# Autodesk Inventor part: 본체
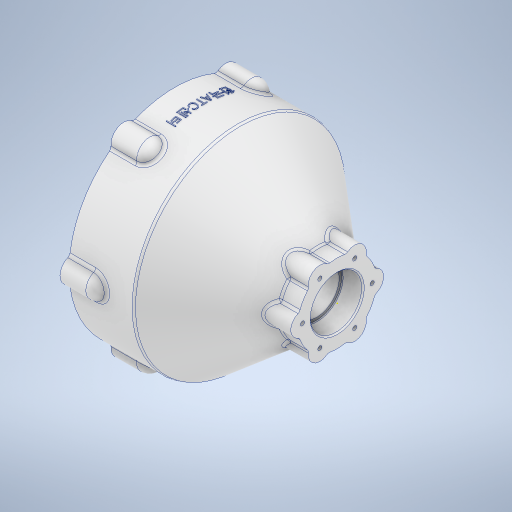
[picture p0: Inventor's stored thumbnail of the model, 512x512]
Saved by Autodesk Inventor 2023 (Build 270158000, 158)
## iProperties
Created: 2026-05
Part Number: 본체
Material: 알루미늄 6061
Document SubType Name: Modeling
Designer: home
Density: 2.7 g/cm^3
Appearance: 알루미늄 - 평지
Mass: 1989.24 g
Surface Area: 1183.24 cm^2
Volume: 736.757 cm^3
Author: home
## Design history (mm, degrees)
sketch "스케치1"
  geometry: L1 (-111.313, 0)-(0, 0); L2 (-126, 0)-(-126, 82); L3 (-126, 82)-(-76, 82); L4 (-76, 82)-(-14.625, 30.5); L5 (-14.625, 30.5)-(0, 30.5); L6 (0, 30.5)-(0, 0); L7 (-126, 73)-(-89, 73); L8 (-89, 73)-(-89, 68); L9 (-89, 68)-(-84, 68); L10 (-84, 68)-(-84, 56); L11 (-84, 56)-(-64, 56); L12 (-64, 56)-(-64, 40); L13 (-64, 40)-(-48, 40); L14 (-48, 40)-(-48, 37); L15 (-48, 37)-(-44, 37); L16 (-44, 37)-(-44, 20); L17 (-44, 20)-(-32, 20); L18 (-32, 20)-(-32, 17.5); L19 (-32, 17.5)-(-16, 17.5); L20 (-16, 17.5)-(-16, 20); L21 (-16, 20)-(0, 20); 2 further points
  constraints: 42 end point, 15 perpendicular, 5 point on line, 2 horizontal, 2 midpoint, 1 parallel, 1 vertical
  dimensions: "d0" = 126 distance from line of L1.end L2; "d1" = 164 diameter of point (-101, 82) L1; "d2" = 146 diameter of L7 L1; "d3" = 136 diameter of L9 L1; "d4" = 112 diameter of L11 L1; "d5" = 80 diameter of L13 L1; "d6" = 74 diameter of L15 L1; "d7" = 40 diameter of L17 L1; "d9" = 16 horizontal distance of L1.end point (-16, 18.75); "d10" = 37 distance of L7.start L7.end; "d11" = 94 distance from line of L2.start L18; "d12" = 12 distance of L16.end L17.end; "d16" = 50 distance of L2.end L3.end; "d17" = 126 horizontal distance of L1.end L2.end (derived); "d18" = 40 deg angle of L4 L3; "d19" = 61 diameter of L5 L1; "d20" = 40 diameter of L21 L1 (derived); "d21" = 5 distance of L8.end L9.end; "d22" = 25 distance between parallel lines of L12 L8; "d23" = 16 distance of L12.end L13.end; "d24" = 4 distance of L14.end L15.end (derived); "d25" = 35 diameter of L19 L1
revolve "회전1" sketch "스케치1" stored, may be unused: angle "d26" = 90 deg
sketch "스케치2"
  geometry: L1 (0, 0)-(79, 0); A1 r 79 centre (0, 0) between (78.367, -9.98) and (78.367, 9.98); A2 r 10 centre (79, 0) between (78.367, -9.98) and (78.367, 9.98); A3 r 79 centre (0, 0) between (78.367, -9.98) and (78.367, 9.98); 2 further points
  constraints: 8 point on circle, 4 coincident, 3 centre point, 2 end point, 1 horizontal
  dimensions: "d27" = 158 diameter of A1; "d28" = 20 diameter of A2
extrude "돌출1" join sketch "스케치2" distance "d29" = 20; taper "d30" = 0 deg
sketch "스케치4"
  geometry: L1 (-79, 0)-(0, 0)
  constraints: 2 end point, 1 horizontal
  dimensions: "d41" = 79 distance of L1.start L1.end
hole "구멍2" sketch "스케치4" at (0, 0) diameter "d42" = 4.917; stored, may be unused: countersink angle "d46" = 90 deg, drill point angle "d48" = 118 deg; dims "d43" = 12, "d44" = 4, "d45" = 2, "d47" = 14
sketch "스케치5"
  geometry: L1 (0, 0)-(62, 0)
  constraints: 2 end point, 1 horizontal
  dimensions: "d52" = 62 distance of L1.start L1.end
hole "구멍3" sketch "스케치5" at (62, 0) diameter "d53" = 3.242; stored, may be unused: countersink angle "d57" = 90 deg, drill point angle "d59" = 118 deg; dims "d54" = 8, "d55" = 4, "d56" = 2, "d58" = 10
sketch "스케치6"
  geometry: A1 r 27 centre (0, 0) between (-25.5, 8.874) and (-25.5, -8.874); A2 r 9 centre (-27, 0) between (-25.5, 8.874) and (-25.5, -8.874); A3 r 27 centre (0, 0) between (-25.5, 8.874) and (-25.5, -8.874); 1 further point
  constraints: 8 point on circle, 3 centre point, 2 coincident
  dimensions: "d63" = 54 diameter of A1; "d64" = 18 diameter of A2
extrude "돌출2" join sketch "스케치6" stored distance "d65" = 20; taper "d66" = 0 deg
sketch "스케치7"
  geometry: 1 further point
sketch "스케치8"
  geometry: L1 (27, 0)-(0, 0)
  constraints: 2 end point, 1 horizontal
  dimensions: "d70" = 27 distance of L1.start L1.end
hole "구멍4" sketch "스케치8" at (0, 0) diameter "d71" = 3.242; stored, may be unused: countersink angle "d75" = 90 deg, drill point angle "d77" = 118 deg; dims "d72" = 8, "d73" = 4, "d74" = 2, "d76" = 10
fillet "모깎기1" dims "d81" = 3
fillet "모깎기2" dims "d82" = 3
sketch "스케치9"
  geometry: L1 (106, 82)-(106, 81.424) reference; L2 (106, 89)-(106, 81.424) reference; L3 (106, 89)-(106, 89); L4 (106, 89)-(106, 79); L5 (96, 79)-(106, 79); A1 r 10 centre (106, 79) between (106, 89) and (96, 79); 4 further points
  constraints: 6 end point, 2 horizontal, 2 point on circle, 1 centre point, 1 point on line, 1 tangent, 1 vertical
  dimensions: "d83" = 10 distance of L2.start point (96, 89); "d84" = 10 radius of A1
revolve "회전2" sketch "스케치9" stored, may be unused: angle "d85" = 180 deg
fillet "모깎기3" dims "d89" = 3
chamfer "모따기1" distance "d90" = 1; stored, may be unused: second distance "d91" = 2, angle "d92" = 45 deg
fillet "모깎기4" dims "d93" = 0.6
chamfer "모따기2" distance "d94" = 1; stored, may be unused: second distance "d95" = 2, angle "d96" = 45 deg
fillet "모깎기5" dims "d97" = 3
fillet "모깎기6" dims "d98" = 1
chamfer "모따기3" distance "d99" = 1; stored, may be unused: second distance "d100" = 2, angle "d101" = 45 deg
node "작업 평면1"
sketch "스케치10"
  geometry: L1 (25, 30.625)-(25, -30.625) reference; 2 further points
  constraints: 1 horizontal alignment, 1 other
  dimensions: "d102" = 20 distance from line of L1 point (5, 0)
feature "엠보싱1" sketch "스케치10" dims "d0" = 126, "d1" = 164, "d2" = 146, "d3" = 136, "d4" = 112, "d5" = 80, "d6" = 74, "d7" = 40, "d9" = 16, "d10" = 37, "d11" = 94, "d12" = 12, "d16" = 50, "d17" = 126 (derived), "d18" = 40 deg, "d19" = 61, "d20" = 40 (derived), "d21" = 5, "d22" = 25, "d23" = 16, "d24" = 4 (derived), "d25" = 35, "d103" = 0.5, "d104" = 0
node "솔리드1"
pattern_circular "원형 패턴1" dims angle "d32" = 360 deg
pattern_circular "원형 패턴2" dims angle "d50" = 360 deg
pattern_circular "원형 패턴3" dims angle "d61" = 360 deg
pattern_circular "원형 패턴4" dims angle "d68" = 360 deg
pattern_circular "원형 패턴5" dims angle "d79" = 360 deg
pattern_circular "원형 패턴6" dims angle "d87" = 360 deg
feature "A9D066F2-1C7D-4E18-AEED-F7BC21143FA4" dims "d42" = 4.917, "d43" = 12, "d44" = 4, "d45" = 2, "d46" = 90 deg, "d47" = 14, "d48" = 118 deg
